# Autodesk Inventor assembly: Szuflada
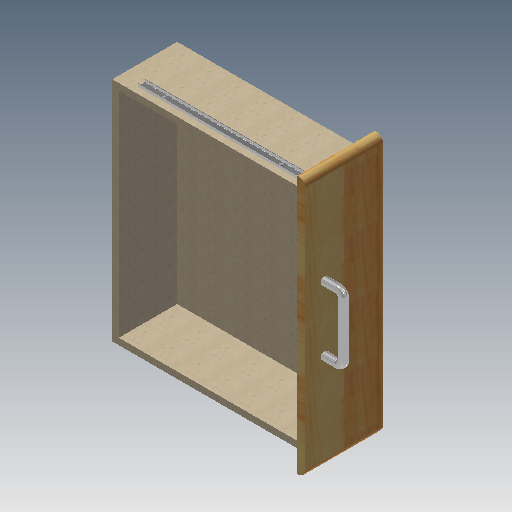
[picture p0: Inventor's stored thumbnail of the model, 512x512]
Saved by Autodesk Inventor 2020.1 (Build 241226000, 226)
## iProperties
Created: 2005-10
Part Number: Szuflada
Document SubType Name: Assembly
Designer: F.Stasiak
Manager: www.cadconsulting.pl
Company: Fabian Stasiak CAD Consulting
Author: F.Stasiak
Subject: Zbiór ćwiczeń. Autodesk Inventor 2020. Kurs podstawowy
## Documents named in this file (6)
- C:\2020_Kurs_podstawowy\R6 Zespoły\Szyki\Szuflada AB.iam
- C:\2020_Kurs_podstawowy\R6 Zespoły\Szyki\Wkręt M3x8.ipt
- C:\2020_Kurs_podstawowy\R6 Zespoły\Szyki\Szyna2.ipt
- C:\2020_Kurs_podstawowy\R6 Zespoły\Szyki\Pudło.ipt
- C:\2020_Kurs_podstawowy\R6 Zespoły\Szyki\Front AB.ipt
- C:\2020_Kurs_podstawowy\R6 Zespoły\Szyki\Uchwyt.ipt
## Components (11 placed, 5 different names)
1. Wkręt M3x8:1
2. Wkręt M3x8:2
3. Wkręt M3x8:3
4. Wkręt M3x8:4
5. Wkręt M3x8:5
6. Wkręt M3x8:6
7. Szyna2:1
8. Szyna2:2
9. Pudło:1
10. Front AB:1
11. Uchwyt:1
